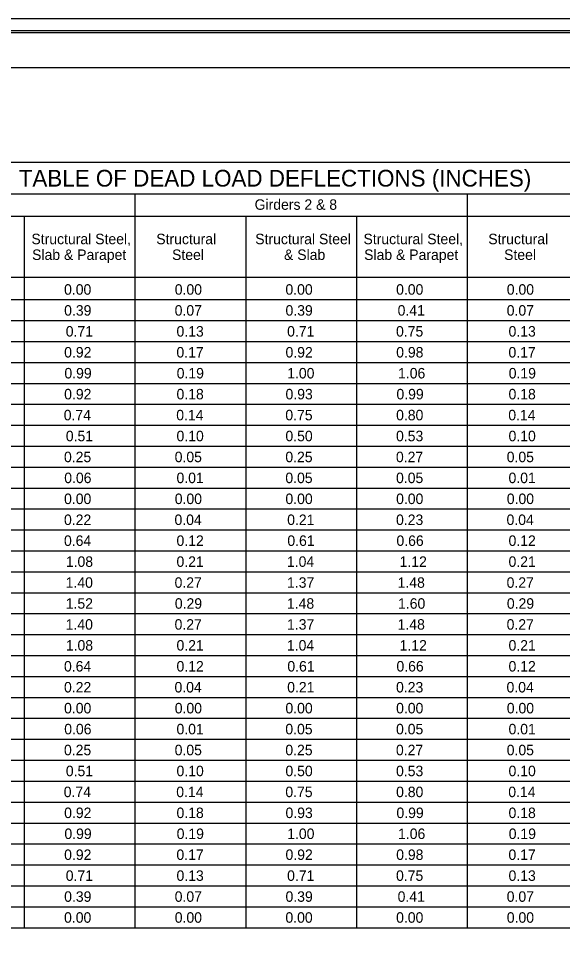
# Model space of a CAD drawing. Extents: x -725.7 to -683.7, y 85.6 to 107.6.
# Drawn here: x -719.13 to -712.63, y 96.51 to 107.6 of the extents above; entities that cross this region are included whole.
import ezdxf

# ---------------------------------------------------------------- set-up
doc = ezdxf.new("R2010")
doc.units = 0
for name, color, linetype in [('border', 7, 'Continuous'), ('Border 2660-Hwy18 - Level 62', 7, 'Continuous'), ('Border 2660-Hwy18 - Level 63', 7, 'Continuous'), ('Level 62 PDF', 7, 'Continuous'), ('Steel', 7, 'Continuous'), ('Text', 7, 'Continuous'), ('Title Text', 7, 'Continuous')]:
    doc.layers.add(name, color=color, linetype=linetype)

msp = doc.modelspace()

# ---------------------------------------------------------------- linework, layer by layer
at = {"layer": 'border'}
msp.add_line((-723.942, 107.01), (-691.93, 107.01), dxfattribs=at)
at = {"layer": 'Border 2660-Hwy18 - Level 62'}
msp.add_lwpolyline([(-725.562, 107.596), (-691.443, 107.596), (-691.443, 85.786), (-725.562, 85.786)], close=True, dxfattribs=at)
at = {"layer": 'Border 2660-Hwy18 - Level 63'}
msp.add_lwpolyline([(-725.673, 107.453), (-691.673, 107.453), (-691.673, 86.083), (-725.673, 86.083)], close=True, dxfattribs=at)
at = {"layer": 'Level 62 PDF'}
msp.add_lwpolyline([(-725.312, 107.429), (-691.193, 107.429), (-691.193, 85.62), (-725.312, 85.62)], close=True, dxfattribs=at)
at = {"layer": 'Steel'}
for p, q in [((-709.806, 105.876), (-723.289, 105.876)), ((-709.806, 105.499), (-723.289, 105.499)), ((-717.738, 105.499), (-717.738, 96.735)), ((-713.772, 105.499), (-713.772, 96.735)), ((-709.806, 105.23), (-721.704, 105.23)), ((-719.06, 105.23), (-719.06, 96.735)), ((-716.416, 105.23), (-716.416, 96.735)), ((-715.094, 105.23), (-715.094, 96.735)), ((-709.806, 104.503), (-723.289, 104.503)), ((-709.806, 104.235), (-722.496, 104.235)), ((-709.806, 103.985), (-722.496, 103.985)), ((-709.806, 103.735), (-722.496, 103.735)), ((-709.806, 103.485), (-722.496, 103.485)), ((-709.806, 103.235), (-722.496, 103.235)), ((-709.806, 102.985), (-722.496, 102.985)), ((-709.806, 102.735), (-722.496, 102.735)), ((-709.806, 102.485), (-722.496, 102.485)), ((-709.806, 102.235), (-722.496, 102.235)), ((-709.806, 101.985), (-722.496, 101.985)), ((-709.806, 101.735), (-722.496, 101.735)), ((-709.806, 101.485), (-722.496, 101.485)), ((-709.806, 101.235), (-722.496, 101.235)), ((-709.806, 100.985), (-722.496, 100.985)), ((-709.806, 100.735), (-722.496, 100.735)), ((-709.806, 100.485), (-722.496, 100.485)), ((-709.806, 100.235), (-722.496, 100.235)), ((-709.806, 99.985), (-722.496, 99.985)), ((-709.806, 99.735), (-722.496, 99.735)), ((-709.806, 99.485), (-722.496, 99.485)), ((-709.806, 99.235), (-722.496, 99.235)), ((-709.806, 98.985), (-722.496, 98.985)), ((-709.806, 98.735), (-722.496, 98.735)), ((-709.806, 98.485), (-722.496, 98.485)), ((-709.806, 98.235), (-722.496, 98.235)), ((-709.806, 97.985), (-722.496, 97.985)), ((-709.806, 97.735), (-722.496, 97.735)), ((-709.806, 97.485), (-722.496, 97.485)), ((-709.806, 97.235), (-722.496, 97.235)), ((-709.806, 96.985), (-722.496, 96.985)), ((-709.806, 96.735), (-723.289, 96.735))]:
    msp.add_line(p, q, dxfattribs=at)

# ---------------------------------------------------------------- texts
at = {"layer": 'Text'}
for s, p in [('Girders 2 & 8', (-716.309, 105.312)), ('Structural Steel,', (-718.975, 104.901)), ('Structural', (-717.484, 104.901)), ('Structural Steel', (-716.302, 104.901)), ('Structural Steel,', (-715.009, 104.901)), ('Structural', (-713.518, 104.901)), ('Slab & Parapet', (-718.967, 104.713)), ('Steel', (-717.295, 104.713)), ('& Slab', (-715.958, 104.713)), ('Slab & Parapet', (-715.001, 104.713)), ('Steel', (-713.329, 104.713)), ('0.00', (-718.585, 104.298)), ('0.00', (-717.263, 104.298)), ('0.00', (-715.941, 104.298)), ('0.00', (-714.619, 104.298)), ('0.00', (-713.297, 104.298)), ('0.39', (-718.584, 104.048)), ('0.07', (-717.264, 104.048)), ('0.39', (-715.94, 104.048)), ('0.41', (-714.601, 104.048)), ('0.07', (-713.298, 104.048)), ('0.71', (-718.565, 103.798)), ('0.13', (-717.242, 103.798)), ('0.71', (-715.921, 103.798)), ('0.75', (-714.62, 103.798)), ('0.13', (-713.276, 103.798)), ('0.92', (-718.584, 103.548)), ('0.17', (-717.243, 103.548)), ('0.92', (-715.94, 103.548)), ('0.98', (-714.618, 103.548)), ('0.17', (-713.277, 103.548)), ('0.99', (-718.581, 103.298)), ('0.19', (-717.24, 103.298)), ('1.00', (-715.92, 103.298)), ('1.06', (-714.596, 103.298)), ('0.19', (-713.274, 103.298)), ('0.92', (-718.584, 103.048)), ('0.18', (-717.242, 103.048)), ('0.93', (-715.94, 103.048)), ('0.99', (-714.615, 103.048)), ('0.18', (-713.276, 103.048)), ('0.74', (-718.589, 102.798)), ('0.14', (-717.245, 102.798)), ('0.75', (-715.942, 102.798)), ('0.80', (-714.619, 102.798)), ('0.14', (-713.279, 102.798)), ('0.51', (-718.564, 102.548)), ('0.10', (-717.242, 102.548)), ('0.50', (-715.941, 102.548)), ('0.53', (-714.62, 102.548)), ('0.10', (-713.276, 102.548)), ('0.25', (-718.586, 102.298)), ('0.05', (-717.264, 102.298)), ('0.25', (-715.942, 102.298)), ('0.27', (-714.621, 102.298)), ('0.05', (-713.298, 102.298)), ('0.06', (-718.583, 102.048)), ('0.01', (-717.242, 102.048)), ('0.05', (-715.942, 102.048)), ('0.05', (-714.62, 102.048)), ('0.01', (-713.276, 102.048)), ('0.00', (-718.585, 101.798)), ('0.00', (-717.263, 101.798)), ('0.00', (-715.941, 101.798)), ('0.00', (-714.619, 101.798)), ('0.00', (-713.297, 101.798)), ('0.22', (-718.586, 101.548)), ('0.04', (-717.266, 101.548)), ('0.21', (-715.92, 101.548)), ('0.23', (-714.62, 101.548)), ('0.04', (-713.3, 101.548)), ('0.64', (-718.586, 101.298)), ('0.12', (-717.242, 101.298)), ('0.61', (-715.918, 101.298)), ('0.66', (-714.615, 101.298)), ('0.12', (-713.276, 101.298)), ('1.08', (-718.564, 101.048)), ('0.21', (-717.242, 101.048)), ('1.04', (-715.923, 101.048)), ('1.12', (-714.577, 101.048)), ('0.21', (-713.276, 101.048)), ('1.40', (-718.566, 100.798)), ('0.27', (-717.265, 100.798)), ('1.37', (-715.922, 100.798)), ('1.48', (-714.601, 100.798)), ('0.27', (-713.299, 100.798)), ('1.52', (-718.565, 100.548)), ('0.29', (-717.262, 100.548)), ('1.48', (-715.923, 100.548)), ('1.60', (-714.596, 100.548)), ('0.29', (-713.296, 100.548)), ('1.40', (-718.566, 100.298)), ('0.27', (-717.265, 100.298)), ('1.37', (-715.922, 100.298)), ('1.48', (-714.601, 100.298)), ('0.27', (-713.299, 100.298)), ('1.08', (-718.564, 100.048)), ('0.21', (-717.242, 100.048)), ('1.04', (-715.923, 100.048)), ('1.12', (-714.577, 100.048)), ('0.21', (-713.276, 100.048)), ('0.64', (-718.586, 99.798)), ('0.12', (-717.242, 99.798)), ('0.61', (-715.918, 99.798)), ('0.66', (-714.615, 99.798)), ('0.12', (-713.276, 99.798)), ('0.22', (-718.586, 99.548)), ('0.04', (-717.266, 99.548)), ('0.21', (-715.92, 99.548)), ('0.23', (-714.62, 99.548)), ('0.04', (-713.3, 99.548)), ('0.00', (-718.585, 99.298)), ('0.00', (-717.263, 99.298)), ('0.00', (-715.941, 99.298)), ('0.00', (-714.619, 99.298)), ('0.00', (-713.297, 99.298)), ('0.06', (-718.583, 99.048)), ('0.01', (-717.242, 99.048)), ('0.05', (-715.942, 99.048)), ('0.05', (-714.62, 99.048)), ('0.01', (-713.276, 99.048)), ('0.25', (-718.586, 98.798)), ('0.05', (-717.264, 98.798)), ('0.25', (-715.942, 98.798)), ('0.27', (-714.621, 98.798)), ('0.05', (-713.298, 98.798)), ('0.51', (-718.564, 98.548)), ('0.10', (-717.242, 98.548)), ('0.50', (-715.941, 98.548)), ('0.53', (-714.62, 98.548)), ('0.10', (-713.276, 98.548)), ('0.74', (-718.589, 98.298)), ('0.14', (-717.245, 98.298)), ('0.75', (-715.942, 98.298)), ('0.80', (-714.619, 98.298)), ('0.14', (-713.279, 98.298)), ('0.92', (-718.584, 98.048)), ('0.18', (-717.242, 98.048)), ('0.93', (-715.94, 98.048)), ('0.99', (-714.615, 98.048)), ('0.18', (-713.276, 98.048)), ('0.99', (-718.581, 97.798)), ('0.19', (-717.24, 97.798)), ('1.00', (-715.92, 97.798)), ('1.06', (-714.596, 97.798)), ('0.19', (-713.274, 97.798)), ('0.92', (-718.584, 97.548)), ('0.17', (-717.243, 97.548)), ('0.92', (-715.94, 97.548)), ('0.98', (-714.618, 97.548)), ('0.17', (-713.277, 97.548)), ('0.71', (-718.565, 97.298)), ('0.13', (-717.242, 97.298)), ('0.71', (-715.921, 97.298)), ('0.75', (-714.62, 97.298)), ('0.13', (-713.276, 97.298)), ('0.39', (-718.584, 97.048)), ('0.07', (-717.264, 97.048)), ('0.39', (-715.94, 97.048)), ('0.41', (-714.601, 97.048)), ('0.07', (-713.298, 97.048)), ('0.00', (-718.585, 96.798)), ('0.00', (-717.263, 96.798)), ('0.00', (-715.941, 96.798)), ('0.00', (-714.619, 96.798)), ('0.00', (-713.297, 96.798))]:
    msp.add_text(s, height=0.125, dxfattribs=at).set_placement(p)
at = {"layer": 'Title Text'}
msp.add_text('TABLE OF DEAD LOAD DEFLECTIONS (INCHES)', height=0.2, dxfattribs=at).set_placement((-719.127, 105.589))

doc.saveas('drawing.dxf')
